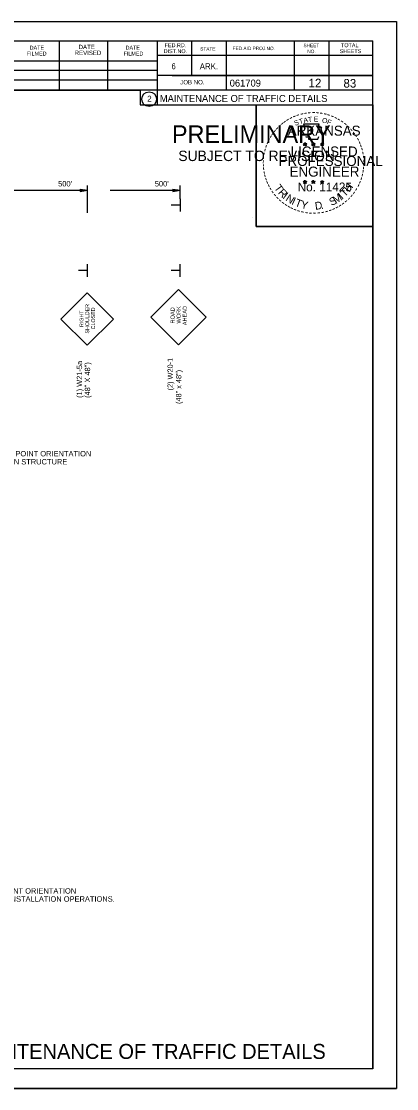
# Model space of a CAD drawing. Extents: x 1397271 to 1411271, y 376395 to 377888.
# Drawn here: x 1410746 to 1411271, y 376395 to 377888 of the extents above; entities that cross this region are included whole.
import ezdxf

# ---------------------------------------------------------------- set-up
doc = ezdxf.new("R2010")
doc.units = 0
for name, color, linetype in [('Default', 7, 'Continuous'), ('R_Border', 7, 'Continuous'), ('R_Border PE', 7, 'Continuous'), ('R_Border Prem', 7, 'Continuous'), ('R_Dimension', 7, 'Continuous'), ('R_Draft', 7, 'Continuous'), ('R_MOT', 7, 'Continuous'), ('R_No Plot', 7, 'Continuous')]:
    doc.layers.add(name, color=color, linetype=linetype)

msp = doc.modelspace()

# ---------------------------------------------------------------- linework, layer by layer
at = {"layer": 'Default'}
for p, q in [((1410828.5, 377653.2), (1410838.9, 377651.7)), ((1410828.5, 377653.2), (1410828.6, 377650.1)), ((1410828.5, 377652.9), (1410837.2, 377651.7)), ((1410828.5, 377652.6), (1410835.4, 377651.6)), ((1410828.5, 377652.4), (1410833.7, 377651.6)), ((1410828.5, 377652.1), (1410831.9, 377651.6)), ((1410828.5, 377651.8), (1410830.2, 377651.6)), ((1410828.5, 377651.1), (1410831.9, 377651.6)), ((1410828.5, 377650.6), (1410835.4, 377651.6)), ((1410828.5, 377650.8), (1410833.7, 377651.6)), ((1410828.5, 377651.4), (1410830.2, 377651.6)), ((1410828.6, 377650.1), (1410838.9, 377651.7)), ((1410828.6, 377650.3), (1410837.2, 377651.7)), ((1410958, 377653.2), (1410968.4, 377651.7)), ((1410958, 377653.2), (1410958, 377650.1)), ((1410958, 377652.9), (1410966.6, 377651.7)), ((1410958, 377652.6), (1410964.9, 377651.6)), ((1410958, 377652.4), (1410963.1, 377651.6)), ((1410958, 377652.1), (1410961.4, 377651.6)), ((1410958, 377651.8), (1410959.7, 377651.6)), ((1410958, 377650.1), (1410968.4, 377651.7)), ((1410958, 377650.3), (1410966.6, 377651.7)), ((1410958, 377651.1), (1410961.4, 377651.6)), ((1410958, 377650.6), (1410964.9, 377651.6)), ((1410958, 377650.8), (1410963.1, 377651.6)), ((1410958, 377651.4), (1410959.7, 377651.6))]:
    msp.add_line(p, q, dxfattribs=at)
at = {"layer": 'R_Border'}
for p, q in [((1409024.8, 377860.7), (1411238.1, 377860.7)), ((1410799.7, 377791.6), (1410799.7, 377859.3)), ((1410867.4, 377791.6), (1410867.4, 377859.3)), ((1410936.4, 377860.7), (1410936.4, 377771.1)), ((1410984.3, 377860.7), (1410984.3, 377812.1)), ((1411032.9, 377860.7), (1411032.9, 377791.6)), ((1411128, 377860.7), (1411128, 377791.6)), ((1411176.5, 377860.7), (1411176.5, 377791.6)), ((1411238.1, 376422.5), (1411238.1, 377860.7)), ((1410662.3, 377832.6), (1410936.4, 377832.6)), ((1411238.1, 377840.1), (1410936.4, 377840.1)), ((1411238.1, 377840.3), (1411238.1, 377840.3)), ((1410662.3, 377819.6), (1410936.4, 377819.6)), ((1410662.3, 377806), (1410936.4, 377806)), ((1411238.1, 377812.1), (1410936.4, 377812.1)), ((1410957.2, 377812.1), (1411238.1, 377812.1)), ((1411238.1, 377791.6), (1410662.3, 377791.6)), ((1410936.4, 377771.1), (1411238.1, 377771.1)), ((1411238.1, 376422.5), (1409024.8, 376422.5))]:
    msp.add_line(p, q, dxfattribs=at)
msp.add_circle((1410925.1, 377779.1), 10.3, dxfattribs=at)
at = {"layer": 'R_Border PE'}
for p, q in [((1411140.7, 377716.8), (1411143.2, 377716.1)), ((1411140.7, 377716.8), (1411142.5, 377716.5)), ((1411140.7, 377716.8), (1411142.4, 377716)), ((1411141.7, 377714), (1411143.2, 377716.1)), ((1411141.7, 377714), (1411142.5, 377715.7)), ((1411141.7, 377714), (1411143.2, 377715.5)), ((1411143.2, 377718.6), (1411142.9, 377716.9)), ((1411143.2, 377716.1), (1411143.2, 377718.6)), ((1411143.2, 377718.6), (1411143.5, 377716.9)), ((1411145.6, 377716.8), (1411143.2, 377716.1)), ((1411144.7, 377714), (1411143.2, 377716.1)), ((1411144.7, 377714), (1411143.2, 377715.5)), ((1411145.6, 377716.8), (1411143.6, 377716.5)), ((1411144.7, 377714), (1411143.7, 377716)), ((1411145.6, 377716.8), (1411144.2, 377716.1)), ((1411152.4, 377716.8), (1411154.9, 377716.1)), ((1411152.4, 377716.8), (1411154.2, 377716.5)), ((1411152.4, 377716.8), (1411154.1, 377716)), ((1411153.3, 377714), (1411154.9, 377716.1)), ((1411153.3, 377714), (1411154.2, 377715.7)), ((1411153.3, 377714), (1411154.8, 377715.5)), ((1411154.9, 377718.6), (1411154.6, 377716.9)), ((1411156.3, 377714), (1411154.8, 377715.5)), ((1411154.9, 377716.1), (1411154.9, 377718.6)), ((1411154.9, 377718.6), (1411155.2, 377716.9)), ((1411157.3, 377716.8), (1411154.9, 377716.1)), ((1411156.3, 377714), (1411154.9, 377716.1)), ((1411157.3, 377716.8), (1411155.3, 377716.5)), ((1411156.3, 377714), (1411155.4, 377716)), ((1411157.3, 377716.8), (1411155.9, 377716.1)), ((1411164.8, 377716.8), (1411167.2, 377716)), ((1411164.8, 377716.8), (1411166.5, 377716.4)), ((1411164.8, 377716.8), (1411166.4, 377715.9)), ((1411165.7, 377713.9), (1411167.2, 377716)), ((1411165.7, 377713.9), (1411166.6, 377715.6)), ((1411165.7, 377713.9), (1411167.2, 377715.4)), ((1411167.2, 377718.5), (1411166.9, 377716.8)), ((1411167.2, 377716), (1411167.2, 377718.5)), ((1411167.2, 377718.5), (1411167.6, 377716.8)), ((1411169.6, 377716.8), (1411167.2, 377716)), ((1411168.7, 377713.9), (1411167.2, 377716)), ((1411168.7, 377713.9), (1411167.2, 377715.4)), ((1411169.6, 377716.8), (1411167.6, 377716.4)), ((1411168.7, 377713.9), (1411167.7, 377715.9)), ((1411169.6, 377716.8), (1411168.2, 377716)), ((1411140.7, 377663.8), (1411143.1, 377663.1)), ((1411140.7, 377663.8), (1411142.5, 377663.5)), ((1411140.7, 377663.8), (1411142.4, 377663)), ((1411143.1, 377665.6), (1411142.9, 377663.8)), ((1411143.1, 377663.1), (1411143.1, 377665.6)), ((1411143.1, 377665.6), (1411143.5, 377663.9)), ((1411145.6, 377663.8), (1411143.1, 377663.1)), ((1411145.6, 377663.8), (1411143.6, 377663.5)), ((1411145.6, 377663.8), (1411144.1, 377663.1)), ((1411152.4, 377663.8), (1411154.8, 377663.1)), ((1411152.4, 377663.8), (1411154.2, 377663.5)), ((1411152.4, 377663.8), (1411154, 377663)), ((1411154.8, 377665.6), (1411154.5, 377663.8)), ((1411154.8, 377663.1), (1411154.8, 377665.6)), ((1411154.8, 377665.6), (1411155.2, 377663.9)), ((1411157.3, 377663.8), (1411154.8, 377663.1)), ((1411157.3, 377663.8), (1411155.3, 377663.5)), ((1411157.3, 377663.8), (1411155.8, 377663.1)), ((1411164.8, 377663.8), (1411167.2, 377663)), ((1411164.8, 377663.8), (1411166.5, 377663.4)), ((1411164.8, 377663.8), (1411166.4, 377662.9)), ((1411167.2, 377665.5), (1411166.9, 377663.8)), ((1411167.2, 377663), (1411167.2, 377665.5)), ((1411167.2, 377665.5), (1411167.5, 377663.8)), ((1411169.6, 377663.8), (1411167.2, 377663)), ((1411169.6, 377663.8), (1411167.6, 377663.4)), ((1411169.6, 377663.8), (1411168.2, 377663)), ((1411141.6, 377661), (1411143.1, 377663.1)), ((1411141.6, 377661), (1411142.5, 377662.7)), ((1411141.6, 377661), (1411143.1, 377662.5)), ((1411144.6, 377661), (1411143.1, 377663.1)), ((1411144.6, 377661), (1411143.1, 377662.5)), ((1411144.6, 377661), (1411143.7, 377663)), ((1411153.3, 377661), (1411154.8, 377663.1)), ((1411153.3, 377661), (1411154.2, 377662.7)), ((1411153.3, 377661), (1411154.8, 377662.5)), ((1411156.3, 377661), (1411154.8, 377663.1)), ((1411156.3, 377661), (1411154.8, 377662.5)), ((1411156.3, 377661), (1411155.4, 377663)), ((1411165.7, 377660.9), (1411167.2, 377663)), ((1411165.7, 377660.9), (1411166.6, 377662.6)), ((1411165.7, 377660.9), (1411167.2, 377662.4)), ((1411168.7, 377660.9), (1411167.2, 377663)), ((1411168.7, 377660.9), (1411167.2, 377662.4)), ((1411168.7, 377660.9), (1411167.7, 377662.9))]:
    msp.add_line(p, q, dxfattribs=at)
for points in [[(1411141, 377744), (1411142.9, 377738.2)], [(1411165.6, 377737.5), (1411166.6, 377739.5), (1411161.8, 377739.4), (1411162.8, 377744), (1411141, 377744)], [(1411144.5, 377727), (1411144.5, 377726.4), (1411148.4, 377726.3), (1411148, 377723), (1411161.1, 377723), (1411162.5, 377726.7)], [(1411143.2, 377718.6), (1411144.7, 377714), (1411140.7, 377716.8), (1411145.6, 377716.8), (1411141.7, 377714), (1411143.2, 377718.6)], [(1411154.9, 377718.6), (1411156.3, 377714), (1411152.4, 377716.8), (1411157.3, 377716.8), (1411153.3, 377714), (1411154.9, 377718.6)], [(1411167.2, 377718.5), (1411168.7, 377713.9), (1411164.8, 377716.8), (1411169.6, 377716.8), (1411165.7, 377713.9), (1411167.2, 377718.5)], [(1411143.1, 377665.6), (1411144.6, 377661), (1411140.7, 377663.8), (1411145.6, 377663.8), (1411141.6, 377661), (1411143.1, 377665.6)], [(1411154.8, 377665.6), (1411156.3, 377661), (1411152.4, 377663.8), (1411157.3, 377663.8), (1411153.3, 377661), (1411154.8, 377665.6)], [(1411167.2, 377665.5), (1411168.7, 377660.9), (1411164.8, 377663.8), (1411169.6, 377663.8), (1411165.7, 377660.9), (1411167.2, 377665.5)]]:
    msp.add_lwpolyline(points, dxfattribs=at)
for centre, radius in [((1411143.2, 377716.1), 1.21), ((1411143.2, 377716.1), 1.01), ((1411143.2, 377716.1), 0.81), ((1411143.2, 377716.1), 0.694), ((1411143.2, 377716.1), 0.523), ((1411143.2, 377716.1), 0.347), ((1411143.2, 377716.1), 0.208), ((1411154.9, 377716.1), 1.21), ((1411154.9, 377716.1), 1.01), ((1411154.9, 377716.1), 0.81), ((1411154.9, 377716.1), 0.694), ((1411154.9, 377716.1), 0.523), ((1411154.9, 377716.1), 0.347), ((1411154.9, 377716.1), 0.208), ((1411167.2, 377716), 1.21), ((1411167.2, 377716), 1.01), ((1411167.2, 377716), 0.81), ((1411167.2, 377716), 0.694), ((1411167.2, 377716), 0.523), ((1411167.2, 377716), 0.347), ((1411167.2, 377716), 0.208), ((1411143.1, 377663), 1.21), ((1411143.1, 377663), 1.01), ((1411143.1, 377663), 0.81), ((1411143.1, 377663), 0.694), ((1411154.8, 377663), 1.21), ((1411154.8, 377663), 1.01), ((1411154.8, 377663), 0.81), ((1411154.8, 377663), 0.694), ((1411167.2, 377663), 1.21), ((1411167.2, 377663), 1.01), ((1411167.2, 377663), 0.81), ((1411167.2, 377663), 0.694), ((1411143.1, 377663), 0.523), ((1411143.1, 377663), 0.347), ((1411143.1, 377663), 0.208), ((1411154.8, 377663), 0.523), ((1411154.8, 377663), 0.347), ((1411154.8, 377663), 0.208), ((1411167.2, 377663), 0.523), ((1411167.2, 377663), 0.347), ((1411167.2, 377663), 0.208)]:
    msp.add_circle(centre, radius, dxfattribs=at)
at = {"layer": 'R_Dimension'}
for p, q in [((1410650.6, 377651.7), (1410838.9, 377651.7)), ((1410838.9, 377620), (1410838.9, 377658.5)), ((1410870.5, 377651.7), (1410968.4, 377651.7)), ((1410968.4, 377639.6), (1410968.4, 377658.5))]:
    msp.add_line(p, q, dxfattribs=at)
at = {"layer": 'R_MOT'}
for p, q in [((1410968.4, 377639.6), (1410968.4, 377621.7)), ((1410968.4, 377630.7), (1410955.9, 377630.7)), ((1410838.8, 377530.6), (1410838.9, 377548.4)), ((1410968.4, 377530.6), (1410968.4, 377548.4)), ((1410838.8, 377539.5), (1410826.4, 377539.5)), ((1410968.4, 377539.5), (1410955.9, 377539.5)), ((1410838.3, 377508.1), (1410801.7, 377471.5)), ((1410838.3, 377508.1), (1410875, 377471.5)), ((1410927.5, 377474.1), (1410966.2, 377512.7)), ((1411004.8, 377474.1), (1410966.2, 377512.7)), ((1410801.7, 377471.5), (1410838.3, 377434.8)), ((1410875, 377471.5), (1410838.3, 377434.8)), ((1410966.2, 377435.4), (1410927.5, 377474.1)), ((1410966.2, 377435.4), (1411004.8, 377474.1))]:
    msp.add_line(p, q, dxfattribs=at)
at = {"layer": 'R_No Plot'}
for p, q in [((1408938, 377888), (1411271.4, 377888)), ((1411070.4, 377613.9), (1411070.4, 377613.9)), ((1408938, 376394.6), (1411271.4, 376394.6))]:
    msp.add_line(p, q, dxfattribs=at)
for points in [[(1408938, 377888), (1411271.4, 377888), (1411271.4, 376394.6), (1408938, 376394.6)], [(1410662.3, 377860.7), (1410662.3, 377791.6), (1410912.4, 377791.6), (1410912.4, 377771.1), (1411074.8, 377771.1), (1411074.8, 377600.8), (1411238.1, 377600.8), (1411238.1, 376422.5), (1409024.8, 376422.5), (1409024.8, 377860.7)], [(1411074.8, 377771.3), (1411238.1, 377771.3), (1411238.1, 377600.8), (1411074.8, 377600.8)]]:
    msp.add_lwpolyline(points, close=True, dxfattribs=at)

# ---------------------------------------------------------------- texts
at = {"layer": 'R_Border'}
for s, height, p in [('FILMED', 5.47, (1410753.9, 377840.1)), ('DATE', 5.47, (1410757.9, 377848.4)), ('REVISED', 6.15, (1410820.9, 377840.8)), ('DATE', 6.15, (1410826.4, 377849.1)), ('FILMED', 5.47, (1410889.3, 377840.1)), ('DATE', 5.47, (1410892.1, 377848.4)), ('DIST.NO.', 5.47, (1410945.4, 377843.5)), ('FED.RD.', 5.47, (1410946.8, 377851.8)), ('STATE', 4.79, (1410996.6, 377847)), ('FED.AID PROJ.NO.', 4.788, (1411041.9, 377847.7)), ('SHEET', 4.79, (1411141, 377851.8)), ('NO.', 4.79, (1411146.4, 377843.5)), ('SHEETS', 5.47, (1411191.7, 377843.5)), ('TOTAL', 5.47, (1411193.6, 377851.8)), ('6', 8.21, (1410956.3, 377821)), ('ARK.', 8.21, (1410995.9, 377821)), ('JOB NO.', 6.15, (1410968.6, 377799.8)), ('061709', 9.8, (1411037.8, 377796.7)), ('2', 8.21, (1410922.5, 377775.7)), ('MAINTENANCE OF TRAFFIC DETAILS', 9.8, (1410940, 377775.2)), ('APPROXIMATED FOR I-30 OVERHEAD SIGN STRUCTURE ', 7.565, (1410524.4, 377268)), ('NOTE: DRAWING NOT TO SCALE.  NORTH POINT ORIENTATION ', 7.565, (1410524.4, 377279.3)), ('APPROXIMATED FOR HWY. 270 GUARDRAIL INSTALLATION OPERATIONS.  ', 7.565, (1410503.2, 376656.2)), ('NOTE: DRAWING NOT TO SCALE.  NORTH POINT ORIENTATION ', 7.565, (1410503.2, 376667.5)), ('MAINTENANCE OF TRAFFIC DETAILS', 21, (1410669.8, 376436.2))]:
    msp.add_text(s, height=height, dxfattribs=at).set_placement(p)
at = {"layer": 'R_Border PE'}
for s, height, rotation, p in [('-', 11.2, 28.7918, (1411123.4, 377747.8)), ('-', 11.2, 24.3072, (1411127.8, 377750)), ('-', 11.2, 19.1761, (1411132.2, 377751.9)), ('-', 11.2, 13.6302, (1411137.5, 377753.6)), ('A', 7, 11.2132, (1411141.7, 377745.8)), ('-', 11.2, 10.2193, (1411142.2, 377754.7)), ('T', 7, 6.0228, (1411147.6, 377747)), ('-', 11.2, 5.8968, (1411147.3, 377755.5)), ('-', 11.2, 0.1862, (1411152.8, 377756)), ('E', 7, 0.8323, (1411155.4, 377747.7)), ('-', 11.2, 357.743, (1411157.8, 377755.9)), ('-', 11.2, 352.1617, (1411163, 377755.5)), ('-', 11.2, 347.2049, (1411168.1, 377754.7)), ('-', 11.2, 342.3362, (1411172.5, 377753.6)), ('-', 11.2, 337.8551, (1411177.6, 377752)), ('-', 11.2, 334.1211, (1411182.1, 377750.1)), ('-', 11.2, 48.4231, (1411105.7, 377733.5)), ('-', 11.2, 42.9622, (1411108.8, 377736.9)), ('-', 11.2, 38.9507, (1411111.8, 377739.8)), ('-', 11.2, 36.2317, (1411115.2, 377742.4)), ('-', 11.2, 34.0636, (1411119.2, 377745.2)), ('S', 7, 21.594, (1411129.5, 377741.7)), ('T', 7, 16.4036, (1411135.9, 377744.1)), ('O', 7, 350.4515, (1411166.6, 377746.3)), ('F', 7, 340.0707, (1411173.3, 377744.7)), ('-', 11.2, 329.6409, (1411186.1, 377748.2)), ('-', 11.2, 325.8627, (1411190.6, 377745.6)), ('-', 11.2, 320.5297, (1411194.9, 377742.7)), ('-', 11.2, 315.5786, (1411199.1, 377739.2)), ('-', 11.2, 62.8713, (1411095.5, 377718.1)), ('-', 11.2, 58.0706, (1411097.7, 377722.4)), ('-', 11.2, 54.2325, (1411099.9, 377726.1)), ('-', 11.2, 50.6142, (1411102.8, 377730.1)), ('-', 11.2, 309.8797, (1411203.1, 377735.4)), ('-', 11.2, 306.6522, (1411206.7, 377731.2)), ('-', 9.8, 303.6753, (1411210.1, 377727.2)), ('-', 11.2, 299.6684, (1411212.4, 377723)), ('-', 11.2, 75.461, (1411090.8, 377704.5)), ('-', 11.2, 72.3945, (1411092.1, 377709.5)), ('-', 11.2, 67.7743, (1411093.7, 377713.9)), ('-', 11.2, 294.6628, (1411214.6, 377718.7)), ('-', 11.2, 290.5728, (1411216.4, 377714.6)), ('-', 11.2, 285.1233, (1411218.1, 377710.6)), ('-', 11.2, 89.0622, (1411089.1, 377689.7)), ('-', 11.2, 85.1863, (1411089.3, 377694.6)), ('-', 11.2, 81.2013, (1411089.8, 377699.5)), ('-', 11.2, 280.5493, (1411219.5, 377705.4)), ('-', 11.2, 276.5962, (1411220.6, 377700)), ('-', 11.2, 274.3301, (1411221, 377694.9)), ('-', 11.2, 94.1959, (1411089.4, 377684.7)), ('-', 11.2, 98.9479, (1411089.9, 377680)), ('-', 11.2, 260.9953, (1411220.6, 377681.3)), ('-', 11.2, 263.5172, (1411221.1, 377685.9)), ('-', 11.2, 269.9407, (1411221.3, 377690.5)), ('-', 11.2, 101.7149, (1411090.8, 377674.9)), ('-', 11.2, 105.4578, (1411091.9, 377670.7)), ('-', 11.2, 109.0874, (1411093.5, 377666.3)), ('-', 11.2, 114.0643, (1411095.2, 377662.1)), ('-', 11.2, 247.8887, (1411217, 377666.8)), ('-', 11.2, 252.8681, (1411218.6, 377671.5)), ('-', 11.2, 255.7626, (1411219.9, 377676.5)), ('-', 11.2, 115.7289, (1411097.4, 377657.8)), ('-', 11.2, 120.4471, (1411099.9, 377653.7)), ('-', 11.2, 125.8934, (1411102.7, 377649.7)), ('T', 10.8, 306.0406, (1411099.5, 377654.9)), ('R', 10.8, 314.005, (1411104.8, 377647.6)), ('I', 10.8, 321.9694, (1411111.1, 377641.1)), ('T', 10.8, 46.6444, (1411199.1, 377641.6)), ('H', 10.8, 54.6088, (1411205.3, 377648.2)), ('-', 11.2, 233.8452, (1411209.6, 377652.5)), ('-', 11.2, 239.0712, (1411212.4, 377657.1)), ('-', 11.2, 244.6197, (1411215.2, 377662.4)), ('-', 11.2, 130.7181, (1411105.9, 377645.9)), ('-', 11.2, 134.2238, (1411109.5, 377642.1)), ('-', 11.2, 138.9338, (1411113.2, 377638.8)), ('-', 11.2, 144.6463, (1411117.1, 377636)), ('N', 10.8, 326.5002, (1411115.1, 377637.8)), ('I', 10.8, 335.3603, (1411123.5, 377632.3)), ('T', 10.8, 339.8912, (1411128.2, 377630)), ('Y', 10.8, 347.8556, (1411136.7, 377626.8)), ('D', 10.8, 6.3969, (1411157.6, 377624.3)), ('S', 10.8, 26.9312, (1411180.3, 377629.5)), ('M', 10.8, 32.6563, (1411186.2, 377632.3)), ('I', 10.8, 42.1136, (1411195.1, 377638.2)), ('-', 11.2, 215.7363, (1411195.8, 377637.8)), ('-', 11.2, 221.0851, (1411199.6, 377641.1)), ('-', 11.2, 225.7653, (1411203.3, 377644.6)), ('-', 11.2, 231.2538, (1411206.6, 377648.6)), ('-', 11.2, 148.0898, (1411121, 377633.4)), ('-', 11.2, 151.5704, (1411125.1, 377631.1)), ('-', 11.2, 154.6002, (1411128.7, 377629.4)), ('-', 11.2, 158.5612, (1411133.1, 377627.6)), ('-', 11.2, 162.7983, (1411137.9, 377626.1)), ('-', 11.2, 167.5555, (1411142.9, 377625)), ('-', 11.2, 173.1155, (1411148.3, 377624.2)), ('-', 11.2, 176.5183, (1411153.6, 377623.8)), ('-', 11.2, 181.5918, (1411158.8, 377623.9)), ('-', 11.2, 185.8167, (1411164.4, 377624.5)), ('-', 11.2, 191.2858, (1411169.6, 377625.4)), ('.', 10.8, 13.7642, (1411165.9, 377625.2)), ('-', 11.2, 195.4743, (1411174.7, 377626.8)), ('-', 11.2, 200.7184, (1411179.4, 377628.5)), ('-', 11.2, 204.2516, (1411183.8, 377630.4)), ('-', 11.2, 207.3568, (1411188.1, 377632.6)), ('-', 11.2, 212.2491, (1411192, 377635.1))]:
    msp.add_text(s, height=height, rotation=rotation, dxfattribs=at).set_placement(p)
for s, height, p in [('ARKANSAS', 14, (1411119, 377728)), ('LICENSED', 14, (1411123.2, 377698.9)), ('DWB', 0.07, (1411143.1, 377716)), ('DWB', 0.07, (1411154.8, 377716)), ('DWB', 0.07, (1411167.1, 377716)), ('PROFESSIONAL', 14, (1411106.2, 377685.6)), ('ENGINEER', 14, (1411121.5, 377670.7)), ('No. 11425', 12.3, (1411132.9, 377650.1)), ('DWB', 0.07, (1411143.1, 377663)), ('DWB', 0.07, (1411154.7, 377663)), ('DWB', 0.07, (1411167.1, 377662.9))]:
    msp.add_text(s, height=height, dxfattribs=at).set_placement(p)
at = {"layer": 'R_Border Prem'}
for s, height, p in [('PRELIMINARY', 24.5, (1410957, 377717.9)), ('DWB', 0.07, (1410958.5, 377730.9)), ('SUBJECT TO REVISION', 14.526, (1410965.9, 377692.5))]:
    msp.add_text(s, height=height, dxfattribs=at).set_placement(p)
at = {"layer": 'R_Dimension'}
for p in [(1410797.7, 377657), (1410933, 377657)]:
    msp.add_text("500'", height=7.57, dxfattribs=at).set_placement(p)
at = {"layer": 'R_Draft'}
for s, p in [('12', (1411148.2, 377795.7)), ('83', (1411197, 377795.3))]:
    msp.add_text(s, height=12, rotation=360, dxfattribs=at).set_placement(p)
at = {"layer": 'R_MOT'}
for s, height, rotation, p in [('SHOULDER', 5.4, 90, (1410841.2, 377451.1)), ('CLOSED', 5.4, 90.0006, (1410849.3, 377457)), ('ROAD', 5.69, 89.9996, (1410960.7, 377465.2)), ('WORK', 5.69, 90, (1410969.2, 377465.1)), ('AHEAD', 5.69, 89.9994, (1410977.8, 377462.8)), ('RIGHT', 5.4, 90.0004, (1410833.1, 377460.2)), ('(1) W21-5a', 7.5, 90, (1410831.3, 377361.1)), ('(2) W20-1', 7.41, 90, (1410958.2, 377371.6)), ('(48" X 48")', 7.5, 90, (1410842.5, 377361.1)), ('(48" x 48")', 7.415, 90, (1410970.1, 377352.6))]:
    msp.add_text(s, height=height, rotation=rotation, dxfattribs=at).set_placement(p)

doc.saveas('drawing.dxf')
